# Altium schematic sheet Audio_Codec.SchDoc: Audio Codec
size A4; Date: Not used; ApprovedBy: Not used; CheckedBy: Not used; Author: Not used; CompanyName: STMicroelectronics; DrawnBy: Not used; Engineer: Not used; Organization: Not used; Address1: Not used; Address2: Not used; Address3: Not used; Address4: Not used; DocumentNumber: Not used; Revision: Not used; SheetNumber: 10; SheetTotal: 23
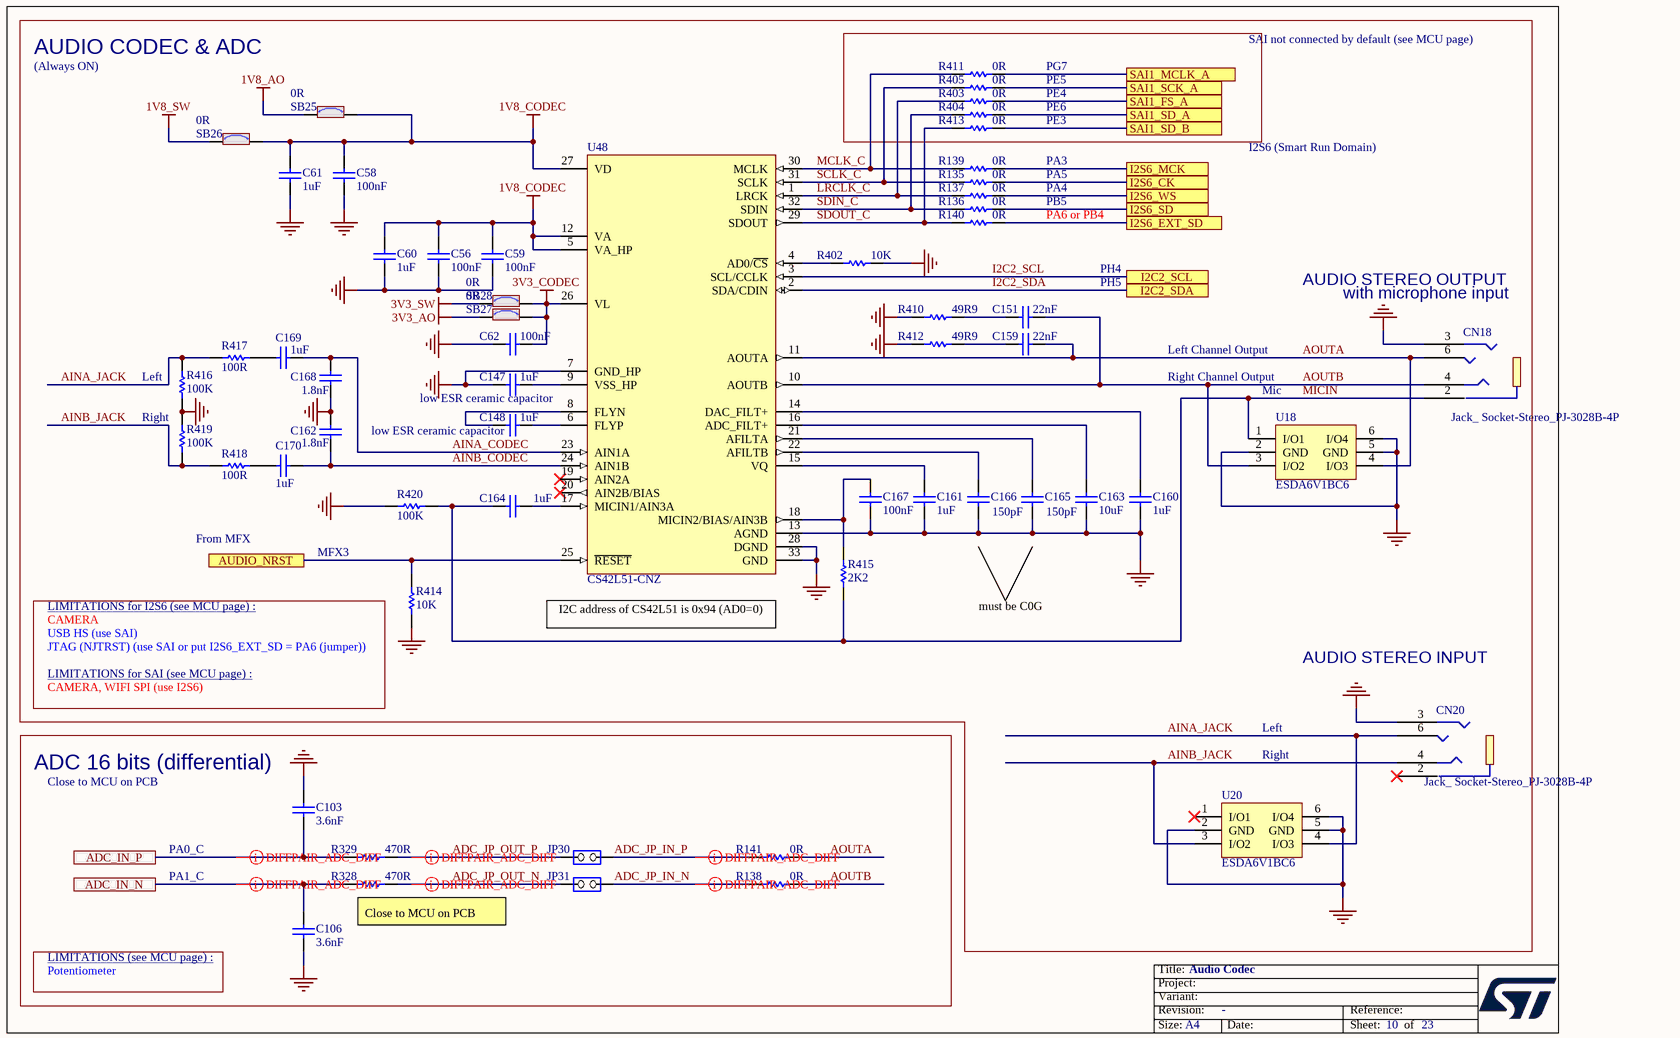
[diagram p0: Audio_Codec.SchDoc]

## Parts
C56  value 100nF  [C0402]  (hidden comment: Capacitor)
C58  value 100nF  [C0402]  (hidden comment: Capacitor)
C59  value 100nF  [C0402]  (hidden comment: Capacitor)
C60  value 1uF  [C0603]  (hidden comment: Capacitor)
C61  value 1uF  [C0603]  (hidden comment: Capacitor)
C62  value 100nF  [C0402]  (hidden comment: Capacitor)
C103  value 3.6nF  [C0603]  (hidden comment: Capacitor)
C106  value 3.6nF  [C0603]  (hidden comment: Capacitor)
C147  value 1uF  [C0603]  (hidden comment: Capacitor)
C148  value 1uF  [C0603]  (hidden comment: Capacitor)
C151  value 22nF  [C0603]  (hidden comment: Capacitor)
C159  value 22nF  [C0603]  (hidden comment: Capacitor)
C160  value 1uF  [C0603]  (hidden comment: Capacitor)
C161  value 1uF  [C0603]  (hidden comment: Capacitor)
C162  value 1.8nF  [C0402]  (hidden comment: Capacitor)
C163  value 10uF  [C0603]  (hidden comment: Capacitor)
C164  value 1uF  [C0603]  (hidden comment: Capacitor)
C165  value 150pF  [C0603]  (hidden comment: Capacitor)
C166  value 150pF  [C0603]  (hidden comment: Capacitor)
C167  value 100nF  [C0402]  (hidden comment: Capacitor)
C168  value 1.8nF  [C0402]  (hidden comment: Capacitor)
C169  value 1uF  [C0402]  (hidden comment: Capacitor)
C170  value 1uF  [C0402]  (hidden comment: Capacitor)
CN18  value Jack_ Socket-Stereo_PJ-3028B-4P  [CON_PHONE-JACK-3P5_HY_PJ3028B]  (hidden comment: Jack_PJ3028B-3_4P)
CN20  value Jack_ Socket-Stereo_PJ-3028B-4P  [CON_PHONE-JACK-3P5_HY_PJ3028B]  (hidden comment: Jack_PJ3028B-3_4P)
JP30  Jumper_Header 2x1  [CON_SAMTEC_TSW-102-07-G-S]  (value not drawn)
JP31  Jumper_Header 2x1  [CON_SAMTEC_TSW-102-07-G-S]  (value not drawn)
R135  value 0R  [R0402]  (hidden comment: Resistor)
R136  value 0R  [R0402]  (hidden comment: Resistor)
R137  value 0R  [R0402]  (hidden comment: Resistor)
R138  value 0R  [R0603]  (hidden comment: Resistor)
R139  value 0R  [R0402]  (hidden comment: Resistor)
R140  value 0R  [R0402]  (hidden comment: Resistor)
R141  value 0R  [R0603]  (hidden comment: Resistor)
R328  value 470R  [R0402]  (hidden comment: Resistor)
R329  value 470R  [R0402]  (hidden comment: Resistor)
R402  value 10K  [R0402]  (hidden comment: Resistor)
R403  value 0R  [R0402]  (hidden comment: Resistor)
R404  value 0R  [R0402]  (hidden comment: Resistor)
R405  value 0R  [R0402]  (hidden comment: Resistor)
R410  value 49R9  [R0603]  (hidden comment: Resistor)
R411  value 0R  [R0402]  (hidden comment: Resistor)
R412  value 49R9  [R0603]  (hidden comment: Resistor)
R413  value 0R  [R0402]  (hidden comment: Resistor)
R414  value 10K  [R0402]  (hidden comment: Resistor)
R415  value 2K2  [R0603]  (hidden comment: Resistor)
R416  value 100K  [R0402]  (hidden comment: Resistor)
R417  value 100R  [R0402]  (hidden comment: Resistor)
R418  value 100R  [R0402]  (hidden comment: Resistor)
R419  value 100K  [R0402]  (hidden comment: Resistor)
R420  value 100K  [R0603]  (hidden comment: Resistor)
SB25  value 0R  [SOLDER-BRIDGE_R0603-0R]  (hidden comment: SB_ON)
SB26  value 0R  [SOLDER-BRIDGE_R0603-0R]  (hidden comment: SB_ON)
SB27  value 0R  [SOLDER-BRIDGE_R0603-0R]  (hidden comment: SB_ON)
SB28  value 0R  [SOLDER-BRIDGE_R0603-0R]  (hidden comment: SB_ON)
U18  ESDA6V1BC6  [ESD_SOT23-6L]
U20  ESDA6V1BC6  [ESD_SOT23-6L]
U48  CS42L51-CNZ  [ICC_QFN32-EPAD_5X5_P050]

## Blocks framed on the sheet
AUDIO CODEC & ADC: C56 C58-C62 C147 C148 C151 C159-C170 CN18 CN20 R135-R137 R139 R140 R402-R405 R410-R420 SB25-SB28 U18 U20 U48
ADC 16 bits (differential): C103 C106 JP30 JP31 R138 R141 R328 R329

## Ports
ADC_IN_N, ADC_IN_P, AUDIO_NRST, I2C2_SCL, I2C2_SDA, I2S6_CK, I2S6_EXT_SD, I2S6_MCK, I2S6_SD, I2S6_WS, SAI1_FS_A, SAI1_MCLK_A, SAI1_SCK_A, SAI1_SD_A, SAI1_SD_B

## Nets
1V8_AO: SB25.1
1V8_CODEC: C56.2 C58.2 C59.2 C60.1 C61.1 SB25.2 SB26.2 U48.5(VA_HP) U48.12(VA) U48.27(VD)
1V8_SW: SB26.1
3V3_AO: SB27.1
3V3_CODEC: C62.1 SB27.2 SB28.2 U48.26(VL)
3V3_SW: SB28.1
GND: C56.1 C58.1 C59.1 C60.2 C61.2 C62.2 C103.2 C106.1 C147.1 C160.1 C161.1 C162.2 C163.1 C165.2 C166.2 C167.2 C168.1 CN18.3 CN20.3 R402.2 R410.1 R412.1 R414.1 R416.1 R419.2 R420.1 U18.2(GND) U18.5(GND) U18.6(I/O4) U20.2(GND) U20.5(GND) U20.6(I/O4) U48.7(GND_HP) U48.13(AGND) U48.28(DGND) U48.33(GND)
ADC_IN_N: C106.2 R328.1 ; port ADC_IN_N
ADC_IN_P: C103.1 R329.1 ; port ADC_IN_P
ADC_JP_IN_N: JP31.1(COMMON) R138.1
ADC_JP_IN_P: JP30.1(COMMON) R141.1
ADC_JP_OUT_N: JP31.2(NO) R328.2
ADC_JP_OUT_P: JP30.2(NO) R329.2
AINA_CODEC: C168.2 C169.2 U48.23(AIN1A)
AINA_JACK: CN20.6 R416.2 R417.1 U20.4(I/O3)
AINB_CODEC: C162.1 C170.2 U48.24(AIN1B)
AINB_JACK: CN20.4 R418.1 R419.1 U20.3(I/O2)
AOUTA: C159.2 CN18.6 R141.2 U18.4(I/O3) U48.11(AOUTA)
AOUTB: C151.2 CN18.4 R138.2 U18.3(I/O2) U48.10(AOUTB)
AUDIO_NRST: R414.2 U48.25(~{RESET}) ; port AUDIO_NRST
I2C2_SCL: U48.3(SCL/CCLK) ; port I2C2_SCL
I2C2_SDA: U48.2(SDA/CDIN) ; port I2C2_SDA
I2S6_CK: R135.2 ; port I2S6_CK
I2S6_EXT_SD: R140.2 ; port I2S6_EXT_SD
I2S6_MCK: R139.2 ; port I2S6_MCK
I2S6_SD: R136.2 ; port I2S6_SD
I2S6_WS: R137.2 ; port I2S6_WS
LRCLK_C: R137.1 R403.1 U48.1(LRCK)
MCLK_C: R139.1 R411.1 U48.30(MCLK)
MICIN: C164.1 CN18.2 R415.1 R420.2 U18.1(I/O1)
SAI1_FS_A: R403.2 ; port SAI1_FS_A
SAI1_MCLK_A: R411.2 ; port SAI1_MCLK_A
SAI1_SCK_A: R405.2 ; port SAI1_SCK_A
SAI1_SD_A: R404.2 ; port SAI1_SD_A
SAI1_SD_B: R413.2 ; port SAI1_SD_B
SCLK_C: R135.1 R405.1 U48.31(SCLK)
SDIN_C: R136.1 R404.1 U48.32(SDIN)
SDOUT_C: R140.1 R413.1 U48.29(SDOUT)
NetC147_2: C147.2 U48.9(VSS_HP)
NetC148_1: C148.1 U48.8(FLYN)
NetC148_2: C148.2 U48.6(FLYP)
NetC151_1: C151.1 R410.2
NetC159_1: C159.1 R412.2
NetC160_2: C160.2 U48.14(DAC_FILT+)
NetC161_2: C161.2 U48.15(VQ)
NetC163_2: C163.2 U48.16(ADC_FILT+)
NetC164_2: C164.2 U48.17(MICIN1/AIN3A)
NetC165_1: C165.1 U48.21(AFILTA)
NetC166_1: C166.1 U48.22(AFILTB)
NetC167_1: C167.1 R415.2 U48.18(MICIN2/BIAS/AIN3B)
NetC169_1: C169.1 R417.2
NetC170_1: C170.1 R418.2
NetR402_1: R402.1 U48.4(AD0/~{CS})

Not connected (* = marked no-connect by the designer): CN20 2*; U20 1(I/O1)*; U48 19(AIN2A)* 20(AIN2B/BIAS)*

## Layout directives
differential pair: ADC_IN_N, ADC_IN_P, ADC_JP_IN_N, ADC_JP_IN_P, ADC_JP_OUT_N, ADC_JP_OUT_P

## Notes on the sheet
- SAI not connected by default (see MCU page)
- (Always ON)
- PE6
- PE4
- PE5
- PG7
- PA5
- PA3
- PE3
- I2S6 (Smart Run Domain)
- PA4
- PA6 or PB4
- PB5
- PH4
- PH5
- AUDIO STEREO OUTPUT
- (near CN18) with microphone input
- (near R416) Left
- Left Channel Output
- Right Channel Output
- Right
- (near C148) low ESR ceramic capacitor
- low ESR ceramic capacitor
- (near U18) Mic
- From MFX
- MFX3
- LIMITATIONS for I2S6 (see MCU page) :
- CAMERA
- USB HS (use SAI)
- (near R414) JTAG (NJTRST) (use SAI or put I2S6_EXT_SD = PA6 (jumper))
- (near U48) I2C address of CS42L51 is 0x94 (AD0=0)
- must be C0G
- LIMITATIONS for SAI (see MCU page) :
- CAMERA, WIFI SPI (use I2S6)
- AUDIO STEREO INPUT
- Close to MCU on PCB
- Left
- PA0_C
- PA1_C
- (near R328) Close to MCU on PCB
- LIMITATIONS (see MCU page) :
- Potentiometer

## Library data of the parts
C56 C58 C59 C62 C167 = MCD-00006: Capacitor, MLCC, 100nF, 16V, X7R, 10%, 0402, T=0.5mm; Manufacturer_Part_Number: CC0402KRX7R7BB104; Manufacturer: YAGEO; Alternate_Manufacturer_Part_Number: GCM155R71C104KA55D; Alternate_Manufacturer: MURATA; Part_Preference: Recommended; Partial_Alternate_Internal_Part_Number: MCD-03299; Provided_By: SUBCO; ECCN_US: EAR99; ECCN_EU: NEC; Component_Country_Of_Origin: China; ID: 2474; Order_Code_RS: 9402047; ShowFields: YES
C60 C61 C147 C148 C160 C161 C164 = MCD-00010: Capacitor, MLCC, 1uF, 16V, X5R, 10%, 0603, T=0,8mm; Manufacturer_Part_Number: CC0603KRX5R7BB105; Manufacturer: YAGEO; Part_Preference: Recommended; Provided_By: SUBCO; ECCN_US: EAR99; ECCN_EU: NEC; Component_Country_Of_Origin: China; ID: 2470; Order_Code_RS: 2370680; ShowFields: YES
C103 C106 = MCD-00716: Capacitor, MLCC, 3.6nF, 50V, C0G, 5%, 0603, T=0,8mm; Manufacturer_Part_Number: C0603C362J5GACTU; Manufacturer: KEMET; Alternate_Manufacturer_Part_Number: GRM1885C1H362JA01D; Alternate_Manufacturer: MURATA; Part_Preference: Recommended; Provided_By: SUBCO; ECCN_US: EAR99; ECCN_EU: NEC; Component_Country_Of_Origin: Mexico; ID: 3031; ShowFields: YES
C151 C159 = MCD-00555: Capacitor, MLCC, 22nF, 10%, 25V, X7R, 0603, T=0,8mm; Manufacturer_Part_Number: CC0603KRX7R8BB223; Manufacturer: YAGEO; Part_Preference: Recommended; Provided_By: SUBCO; ECCN_US: EAR99; ECCN_EU: NEC; Component_Country_Of_Origin: China; ID: 3190; ShowFields: YES
C162 C168 = MCD-00694: Capacitor, MLCC, 1.8nF, 50V, X7R, 10%, 0402, T=0.5mm; Manufacturer_Part_Number: CC0402KRX7R9BB182; Manufacturer: YAGEO; Part_Preference: Recommended; Provided_By: SUBCO; Component_Country_Of_Origin: China; ID: 3045; ShowFields: YES
C163 = MCD-00099: Capacitor, MLCC, 10uF, 10V, X5R, 10%, 0603, T=0,8mm; Manufacturer_Part_Number: GRM188R61A106KE69D; Manufacturer: MURATA; Part_Preference: Recommended; Partial_Alternate_Internal_Part_Number: MCD-03152; Provided_By: SUBCO; ECCN_US: EAR99; ECCN_EU: NEC; Component_Country_Of_Origin: Japan°°; ID: 2770; Order_Code_RS: 2494233; ShowFields: YES
C165 C166 = MCD-00304: Capacitor, MLCC, 150pF, 50V, COG, 5%, 0603, T=0,8mm; Manufacturer_Part_Number: CC0603JRNPO9BN151; Manufacturer: YAGEO; BMS_Part_Number: 9142051; Part_Preference: Recommended; Provided_By: SUBCO; ECCN_US: EAR99; ECCN_EU: NEC; Component_Country_Of_Origin: China; ID: 2568; ShowFields: YES
C169 C170 = MCD-00095: Capacitor, MLCC, 1uF, 6V3, X5R, 10%, 0402, T=0,5mm; Manufacturer_Part_Number: GRM155R61E105KA12; Manufacturer: MURATA; Alternate_Manufacturer_Part_Number: GRM155R60J105KE19; Part_Preference: Recommended; Provided_By: SUBCO; ECCN_US: EAR99; ECCN_EU: NEC; Component_Country_Of_Origin: Japan°°; ID: 2772; Order_Code_RS: 2218855; ShowFields: YES
CN18 CN20 = MCD-00263: Connector Jack Socket Stereo 3.5mm, 4 pins, RA, SMT, Black; Manufacturer_Part_Number: PJ-3028B-4P; Manufacturer: QIAOD; Part_Preference: Recommended; Provided_By: SUBCO; Component_Country_Of_Origin: Unknown; ID: 2608; ShowFields: YES
JP30 JP31 = MCD-00045: Header, 2x1, 2,54mm, VR, TH, Height 5.84mm/2.54mm; Part_Type: Connector; Manufacturer_Part_Number: TSW-102-07-G-S; Manufacturer: SAMTEC; Alternate_Manufacturer_Part_Number: 313102S111116;313102S111116; Alternate_Manufacturer: JIUBABA; LIANYI; Full_Alternate_Internal_Part_Number: MCD-02390; Part_Preference: Recommended; Partial_Alternate_Internal_Part_Number: MCD-02957, MCD-03720; Provided_By: SUBCO; Component_Country_Of_Origin: China, Costa Rica, Malaysia, USA, Vietnam; ID: 2545; Order_Code_RS: 2505044; ShowFields: YES
R135-R137 R139 R140 R403-R405 R411 R413 = MCD-00052: Resistor,0R,0402,5%,1/16W; Manufacturer_Part_Number: RC0402JR-070RL; Manufacturer: YAGEO; Part_Preference: Recommended; Provided_By: SUBCO; ECCN_US: EAR99; ECCN_EU: NEC; Component_Country_Of_Origin: China; ID: 2540; Order_Code_RS: 9232516RL; ShowFields: YES
R138 R141 = MCD-00056: Resistor,0R,0603,5%,1/10W; Manufacturer_Part_Number: RC0603JR-070RL; Manufacturer: YAGEO; Part_Preference: Recommended; Provided_By: SUBCO; ECCN_US: EAR99; ECCN_EU: NEC; Component_Country_Of_Origin: China; ID: 2536; Order_Code_RS: 9233130RL; ShowFields: YES
R328 R329 = MCD-00178: Resistor,470R,0402,1%,1/16W; Manufacturer_Part_Number: RC0402FR-07470RL; Manufacturer: YAGEO; Part_Preference: Recommended; Provided_By: SUBCO; ECCN_US: EAR99; ECCN_EU: NEC; Component_Country_Of_Origin: China; ID: 2689; ShowFields: YES
R402 R414 = MCD-00053: Resistor,10K,0402,1%,1/16W; Manufacturer_Part_Number: RC0402FR-0710KL; Manufacturer: YAGEO; BMS_Part_Number: 9131590; Part_Preference: Recommended; Provided_By: SUBCO; ECCN_US: EAR99; ECCN_EU: NEC; Component_Country_Of_Origin: China; ID: 2539; Order_Code_RS: 9239359; ShowFields: YES
R410 R412 = MCD-00564: Resistor,49R9,0603,1%,1/10W; Manufacturer_Part_Number: RC0603FR-0749R9L; Manufacturer: YAGEO; Part_Preference: Recommended; Provided_By: SUBCO; ECCN_US: EAR99; ECCN_EU: NEC; Component_Country_Of_Origin: China; ID: 3180; ShowFields: YES
R415 = MCD-00349: Resistor,2K2,0603,1%,1/10W; Manufacturer_Part_Number: RC0603FR-072K2L; Manufacturer: YAGEO; Part_Preference: Recommended; Provided_By: SUBCO; ECCN_US: EAR99; ECCN_EU: NEC; Component_Country_Of_Origin: China; ID: 2929; ShowFields: YES
R416 R419 = MCD-00059: Resistor,100K,0402,1%,1/16W; Manufacturer_Part_Number: RC0402FR-07100KL; Manufacturer: YAGEO; Alternate_Manufacturer_Part_Number: RT0402FRE07100KL; Part_Preference: Recommended; Partial_Alternate_Internal_Part_Number: MCD-03301; Provided_By: SUBCO; ECCN_US: EAR99; ECCN_EU: NEC; Component_Country_Of_Origin: China; ID: 2533; Order_Code_RS: 2421891; ShowFields: YES
R417 R418 = MCD-00067: Resistor,100R,0402,1%,1/16W; Manufacturer_Part_Number: RC0402FR-07100RL; Manufacturer: YAGEO; Part_Preference: Recommended; Provided_By: SUBCO; ECCN_US: EAR99; ECCN_EU: NEC; Component_Country_Of_Origin: China; ID: 2527; Order_Code_RS: 9239111; ShowFields: YES
R420 = MCD-00223: Resistor,100K,0603,1%,1/10W; Manufacturer_Part_Number: RC0603FR-07100KL; Manufacturer: YAGEO; Part_Preference: Recommended; Provided_By: SUBCO; ECCN_US: EAR99; ECCN_EU: NEC; Component_Country_Of_Origin: China; ID: 2647; ShowFields: YES
SB25-SB28 = MCD-00071: Solder Bridge ON; Part_Type: Resistor; Manufacturer_Part_Number: RC0603JR-070RL; Manufacturer: YAGEO; Manufacturer_HQ_COO: Unknown; Part_Preference: Recommended; Provided_By: SUBCO; Component_Country_Of_Origin: China; ID: 2521; Order_Code_RS: 199-5647; ShowFields: YES
U18 U20 = MCD-00247: Quad Bidir ESD protection; Manufacturer: STMICROELECTRONICS; Part_Type: Diode; BMS_Part_Number: 9179038; Manufacturer_HQ_COO: EU; Part_Preference: Recommended; Provided_By: SUBCO with ST control; ECCN_US: EAR99; ECCN_EU: NEC; Component_Country_Of_Origin: China; ID: 2624; Order_Code_RS: 248-805; ShowFields: YES
U48 = MCD-00265: Low-Power, Stereo Codec with Headphone Amp; Manufacturer: CIRRUS LOGIC; Part_Type: IC; Part_Preference: Forbidden; Provided_By: SUBCO; ECCN_US: EAR99; ECCN_EU: NEC; Component_Country_Of_Origin: China°; ID: 2602; ShowFields: YES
